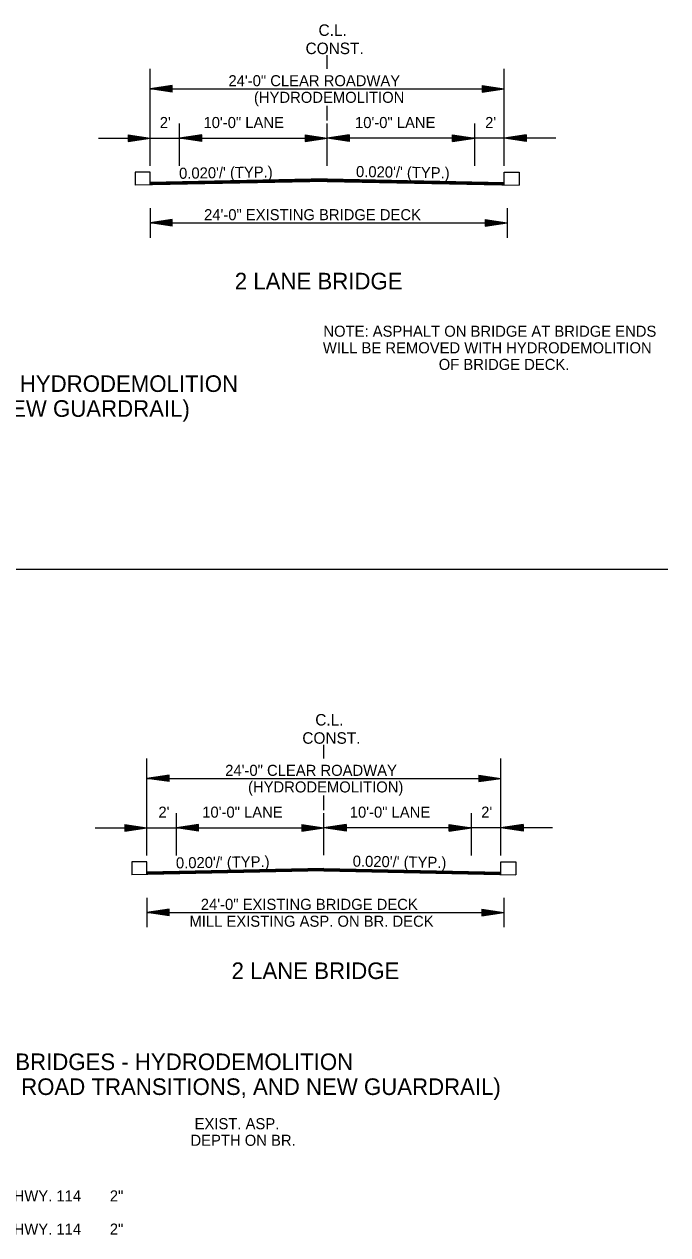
# Model space of a CAD drawing. Extents: x 544259 to 1930787, y -1961343 to 596640.
# Drawn here: x 544789 to 545226, y -1949576 to -1948755 of the extents above; entities that cross this region are included whole.
import ezdxf

# ---------------------------------------------------------------- set-up
doc = ezdxf.new("R2010")
doc.units = 0
doc.layers.add('R_Border', color=7, linetype='Continuous')
doc.layers.add('R_Draft', color=7, linetype='Continuous')

msp = doc.modelspace()

# ---------------------------------------------------------------- linework, layer by layer
at = {"layer": 'R_Border'}
for p, q in [((544864.6, -1948855.05), (544864.59, -1948863.86)), ((544874.77, -1948855.05), (544864.6, -1948855.05)), ((544874.77, -1948863.49), (544874.77, -1948855.05)), ((545114.77, -1948863.49), (545114.77, -1948855.05)), ((545114.77, -1948855.05), (545124.94, -1948855.05)), ((545124.94, -1948855.05), (545124.95, -1948863.86)), ((544266.84, -1949124.25), (545225.68, -1949124.25)), ((544862.4, -1949322.65), (544862.39, -1949331.46)), ((544872.57, -1949322.65), (544862.4, -1949322.65)), ((544872.57, -1949331.09), (544872.57, -1949322.65)), ((545112.57, -1949331.09), (545112.57, -1949322.65)), ((545112.57, -1949322.65), (545122.74, -1949322.65)), ((545122.74, -1949322.65), (545122.75, -1949331.46))]:
    msp.add_line(p, q, dxfattribs=at)
at = {"layer": 'R_Draft'}
for p, q in [((544994.77, -1948785.03), (544994.77, -1948775.73)), ((544874.77, -1948850.81), (544874.77, -1948785.08)), ((545114.77, -1948850.81), (545114.77, -1948785.08)), ((544889.77, -1948796.2), (544874.77, -1948798.45)), ((544874.77, -1948798.45), (545114.77, -1948798.45)), ((544889.77, -1948800.7), (544874.77, -1948798.45)), ((544889.77, -1948796.57), (544877.27, -1948798.45)), ((544889.77, -1948800.32), (544877.27, -1948798.45)), ((544889.77, -1948796.95), (544879.85, -1948798.45)), ((544889.77, -1948799.94), (544879.85, -1948798.45)), ((544889.77, -1948797.33), (544882.35, -1948798.45)), ((544889.77, -1948799.56), (544882.35, -1948798.45)), ((544889.77, -1948797.71), (544884.89, -1948798.45)), ((544889.77, -1948799.17), (544884.89, -1948798.45)), ((544889.77, -1948798.09), (544887.4, -1948798.45)), ((544889.77, -1948798.8), (544887.4, -1948798.45)), ((544889.77, -1948800.7), (544889.77, -1948796.2)), ((545099.77, -1948796.2), (545114.77, -1948798.45)), ((545099.77, -1948796.2), (545099.77, -1948800.7)), ((545099.77, -1948796.57), (545112.26, -1948798.45)), ((545099.77, -1948796.95), (545109.68, -1948798.45)), ((545099.77, -1948797.33), (545107.19, -1948798.45)), ((545099.77, -1948797.72), (545104.64, -1948798.45)), ((545099.77, -1948798.09), (545102.14, -1948798.45)), ((545099.77, -1948800.7), (545114.77, -1948798.45)), ((545099.77, -1948799.18), (545104.64, -1948798.45)), ((545099.77, -1948799.94), (545109.68, -1948798.45)), ((545099.77, -1948800.32), (545112.26, -1948798.45)), ((545099.77, -1948799.56), (545107.19, -1948798.45)), ((545099.77, -1948798.8), (545102.14, -1948798.45)), ((544994.77, -1948819.97), (544994.77, -1948810.1)), ((544894.77, -1948850.81), (544894.77, -1948822.09)), ((544994.77, -1948850.64), (544994.77, -1948822.09)), ((545094.77, -1948850.81), (545094.77, -1948822.09)), ((544839.77, -1948831.98), (544994.77, -1948831.98)), ((544859.77, -1948829.73), (544874.77, -1948831.98)), ((544859.77, -1948829.73), (544859.77, -1948834.23)), ((544859.77, -1948830.11), (544872.26, -1948831.98)), ((544859.77, -1948830.49), (544869.68, -1948831.98)), ((544859.77, -1948830.87), (544867.19, -1948831.98)), ((544859.77, -1948831.26), (544864.64, -1948831.98)), ((544859.77, -1948831.63), (544862.14, -1948831.98)), ((544859.77, -1948834.23), (544874.77, -1948831.98)), ((544859.77, -1948832.72), (544864.64, -1948831.98)), ((544859.77, -1948833.48), (544869.68, -1948831.98)), ((544859.77, -1948833.86), (544872.26, -1948831.98)), ((544859.77, -1948833.1), (544867.19, -1948831.98)), ((544859.77, -1948832.34), (544862.14, -1948831.98)), ((544909.77, -1948829.73), (544894.77, -1948831.98)), ((544909.77, -1948834.23), (544894.77, -1948831.98)), ((544909.77, -1948830.11), (544897.27, -1948831.98)), ((544909.77, -1948833.86), (544897.27, -1948831.98)), ((544909.77, -1948830.49), (544899.85, -1948831.98)), ((544909.77, -1948833.48), (544899.85, -1948831.98)), ((544909.77, -1948830.87), (544902.35, -1948831.98)), ((544909.77, -1948833.1), (544902.35, -1948831.98)), ((544909.77, -1948831.25), (544904.89, -1948831.98)), ((544909.77, -1948832.71), (544904.89, -1948831.98)), ((544909.77, -1948831.63), (544907.4, -1948831.98)), ((544909.77, -1948832.34), (544907.4, -1948831.98)), ((544909.77, -1948834.23), (544909.77, -1948829.73)), ((544979.77, -1948829.73), (544994.77, -1948831.98)), ((544979.77, -1948829.73), (544979.77, -1948834.23)), ((544979.77, -1948830.11), (544992.26, -1948831.98)), ((544979.77, -1948830.49), (544989.68, -1948831.98)), ((544979.77, -1948830.87), (544987.19, -1948831.98)), ((544979.77, -1948831.26), (544984.64, -1948831.98)), ((544979.77, -1948831.63), (544982.14, -1948831.98)), ((544979.77, -1948834.23), (544994.77, -1948831.98)), ((544979.77, -1948832.72), (544984.64, -1948831.98)), ((544979.77, -1948833.48), (544989.68, -1948831.98)), ((544979.77, -1948833.86), (544992.26, -1948831.98)), ((544979.77, -1948833.1), (544987.19, -1948831.98)), ((544979.77, -1948832.34), (544982.14, -1948831.98)), ((545009.77, -1948829.73), (544994.77, -1948831.98)), ((545149.77, -1948831.98), (544994.77, -1948831.98)), ((545009.77, -1948834.23), (544994.77, -1948831.98)), ((545009.77, -1948830.11), (544997.27, -1948831.98)), ((545009.77, -1948833.86), (544997.27, -1948831.98)), ((545009.77, -1948830.49), (544999.85, -1948831.98)), ((545009.77, -1948833.48), (544999.85, -1948831.98)), ((545009.77, -1948830.87), (545002.35, -1948831.98)), ((545009.77, -1948833.1), (545002.35, -1948831.98)), ((545009.77, -1948831.26), (545004.89, -1948831.98)), ((545009.77, -1948832.72), (545004.89, -1948831.98)), ((545009.77, -1948831.63), (545007.4, -1948831.98)), ((545009.77, -1948832.34), (545007.4, -1948831.98)), ((545009.77, -1948829.73), (545009.77, -1948834.23)), ((545079.77, -1948829.73), (545094.77, -1948831.98)), ((545079.77, -1948834.23), (545079.77, -1948829.73)), ((545079.77, -1948830.11), (545092.26, -1948831.98)), ((545079.77, -1948830.49), (545089.68, -1948831.98)), ((545079.77, -1948830.87), (545087.19, -1948831.98)), ((545079.77, -1948831.25), (545084.64, -1948831.98)), ((545079.77, -1948831.63), (545082.14, -1948831.98)), ((545079.77, -1948834.23), (545094.77, -1948831.98)), ((545079.77, -1948832.71), (545084.64, -1948831.98)), ((545079.77, -1948833.48), (545089.68, -1948831.98)), ((545079.77, -1948833.86), (545092.26, -1948831.98)), ((545079.77, -1948833.1), (545087.19, -1948831.98)), ((545079.77, -1948832.34), (545082.14, -1948831.98)), ((545129.77, -1948829.73), (545114.77, -1948831.98)), ((545129.77, -1948834.23), (545114.77, -1948831.98)), ((545129.77, -1948830.11), (545117.27, -1948831.98)), ((545129.77, -1948833.86), (545117.27, -1948831.98)), ((545129.77, -1948830.49), (545119.85, -1948831.98)), ((545129.77, -1948833.48), (545119.85, -1948831.98)), ((545129.77, -1948830.87), (545122.35, -1948831.98)), ((545129.77, -1948833.1), (545122.35, -1948831.98)), ((545129.77, -1948831.26), (545124.89, -1948831.98)), ((545129.77, -1948832.72), (545124.89, -1948831.98)), ((545129.77, -1948831.63), (545127.4, -1948831.98)), ((545129.77, -1948832.34), (545127.4, -1948831.98)), ((545129.77, -1948829.73), (545129.77, -1948834.23)), ((544994.8, -1948861.26), (544864.59, -1948863.86)), ((544994.77, -1948859.59), (544874.77, -1948861.99)), ((544994.77, -1948859.89), (544874.77, -1948862.29)), ((544994.78, -1948860.19), (544874.77, -1948862.59)), ((544994.79, -1948860.49), (544874.77, -1948862.89)), ((544994.79, -1948860.79), (544874.77, -1948863.19)), ((544994.8, -1948861.09), (544874.77, -1948863.49)), ((544994.74, -1948860.79), (545114.77, -1948863.19)), ((544994.74, -1948861.09), (545114.77, -1948863.49)), ((544994.74, -1948861.26), (545124.95, -1948863.86)), ((544994.75, -1948860.49), (545114.77, -1948862.89)), ((544994.76, -1948859.89), (545114.77, -1948862.29)), ((544994.76, -1948860.19), (545114.77, -1948862.59)), ((544994.77, -1948859.59), (545114.77, -1948861.99)), ((544874.77, -1948879.45), (544874.77, -1948899.45)), ((545116.77, -1948879.45), (545116.77, -1948899.45)), ((544889.77, -1948887.2), (544874.77, -1948889.45)), ((544874.77, -1948889.45), (545114.77, -1948889.45)), ((544889.77, -1948891.7), (544874.77, -1948889.45)), ((544889.77, -1948887.57), (544877.27, -1948889.45)), ((544889.77, -1948891.32), (544877.27, -1948889.45)), ((544889.77, -1948887.96), (544879.85, -1948889.45)), ((544889.77, -1948890.94), (544879.85, -1948889.45)), ((544889.77, -1948888.33), (544882.35, -1948889.45)), ((544889.77, -1948890.57), (544882.35, -1948889.45)), ((544889.77, -1948888.71), (544884.89, -1948889.45)), ((544889.77, -1948890.18), (544884.89, -1948889.45)), ((544889.77, -1948889.1), (544887.4, -1948889.45)), ((544889.77, -1948889.8), (544887.4, -1948889.45)), ((544889.77, -1948891.7), (544889.77, -1948887.2)), ((545101.77, -1948887.2), (545116.77, -1948889.45)), ((545101.77, -1948887.2), (545101.77, -1948891.7)), ((545101.77, -1948887.57), (545114.26, -1948889.45)), ((545101.77, -1948887.96), (545111.68, -1948889.45)), ((545101.77, -1948888.33), (545109.19, -1948889.45)), ((545101.77, -1948888.72), (545106.64, -1948889.45)), ((545101.77, -1948889.1), (545104.14, -1948889.45)), ((545101.77, -1948891.7), (545116.77, -1948889.45)), ((545101.77, -1948890.18), (545106.64, -1948889.45)), ((545101.77, -1948890.94), (545111.68, -1948889.45)), ((545101.77, -1948891.32), (545114.26, -1948889.45)), ((545101.77, -1948890.57), (545109.19, -1948889.45)), ((545101.77, -1948889.8), (545104.14, -1948889.45)), ((544992.57, -1949252.63), (544992.57, -1949243.32)), ((544872.57, -1949318.41), (544872.57, -1949252.67)), ((545112.57, -1949318.41), (545112.57, -1949252.67)), ((544887.57, -1949263.79), (544872.57, -1949266.04)), ((544872.57, -1949266.04), (545112.57, -1949266.04)), ((544887.57, -1949268.29), (544872.57, -1949266.04)), ((544887.57, -1949264.17), (544875.08, -1949266.04)), ((544887.57, -1949267.92), (544875.08, -1949266.04)), ((544887.57, -1949264.55), (544877.66, -1949266.04)), ((544887.57, -1949267.53), (544877.66, -1949266.04)), ((544887.57, -1949264.92), (544880.15, -1949266.04)), ((544887.57, -1949267.16), (544880.15, -1949266.04)), ((544887.57, -1949265.31), (544882.7, -1949266.04)), ((544887.57, -1949266.77), (544882.7, -1949266.04)), ((544887.57, -1949265.69), (544885.2, -1949266.04)), ((544887.57, -1949266.39), (544885.2, -1949266.04)), ((544887.57, -1949268.29), (544887.57, -1949263.79)), ((545097.57, -1949263.79), (545112.57, -1949266.04)), ((545097.57, -1949263.79), (545097.57, -1949268.29)), ((545097.57, -1949264.17), (545110.07, -1949266.04)), ((545097.57, -1949264.55), (545107.49, -1949266.04)), ((545097.57, -1949264.92), (545104.99, -1949266.04)), ((545097.57, -1949265.31), (545102.45, -1949266.04)), ((545097.57, -1949265.69), (545099.94, -1949266.04)), ((545097.57, -1949268.29), (545112.57, -1949266.04)), ((545097.57, -1949266.78), (545102.45, -1949266.04)), ((545097.57, -1949267.53), (545107.49, -1949266.04)), ((545097.57, -1949267.92), (545110.07, -1949266.04)), ((545097.57, -1949267.16), (545104.99, -1949266.04)), ((545097.57, -1949266.39), (545099.94, -1949266.04)), ((544992.57, -1949287.56), (544992.57, -1949277.69)), ((544892.57, -1949318.41), (544892.57, -1949289.69)), ((544992.57, -1949318.24), (544992.57, -1949289.69)), ((545092.57, -1949318.41), (545092.57, -1949289.69)), ((544837.57, -1949299.58), (544992.57, -1949299.58)), ((544857.57, -1949297.33), (544872.57, -1949299.58)), ((544857.57, -1949297.33), (544857.57, -1949301.83)), ((544857.57, -1949297.7), (544870.07, -1949299.58)), ((544857.57, -1949298.09), (544867.49, -1949299.58)), ((544857.57, -1949298.46), (544864.99, -1949299.58)), ((544857.57, -1949298.85), (544862.45, -1949299.58)), ((544857.57, -1949299.23), (544859.94, -1949299.58)), ((544857.57, -1949301.83), (544872.57, -1949299.58)), ((544857.57, -1949300.31), (544862.45, -1949299.58)), ((544857.57, -1949301.07), (544867.49, -1949299.58)), ((544857.57, -1949301.45), (544870.07, -1949299.58)), ((544857.57, -1949300.7), (544864.99, -1949299.58)), ((544857.57, -1949299.93), (544859.94, -1949299.58)), ((544907.57, -1949297.33), (544892.57, -1949299.58)), ((544907.57, -1949301.83), (544892.57, -1949299.58)), ((544907.57, -1949297.7), (544895.08, -1949299.58)), ((544907.57, -1949301.45), (544895.08, -1949299.58)), ((544907.57, -1949298.09), (544897.66, -1949299.58)), ((544907.57, -1949301.07), (544897.66, -1949299.58)), ((544907.57, -1949298.46), (544900.15, -1949299.58)), ((544907.57, -1949300.7), (544900.15, -1949299.58)), ((544907.57, -1949298.84), (544902.7, -1949299.58)), ((544907.57, -1949300.31), (544902.7, -1949299.58)), ((544907.57, -1949299.23), (544905.2, -1949299.58)), ((544907.57, -1949299.93), (544905.2, -1949299.58)), ((544907.57, -1949301.83), (544907.57, -1949297.33)), ((544977.57, -1949297.33), (544992.57, -1949299.58)), ((544977.57, -1949297.33), (544977.57, -1949301.83)), ((544977.57, -1949297.7), (544990.07, -1949299.58)), ((544977.57, -1949298.09), (544987.49, -1949299.58)), ((544977.57, -1949298.46), (544984.99, -1949299.58)), ((544977.57, -1949298.85), (544982.45, -1949299.58)), ((544977.57, -1949299.23), (544979.94, -1949299.58)), ((544977.57, -1949301.83), (544992.57, -1949299.58)), ((544977.57, -1949300.31), (544982.45, -1949299.58)), ((544977.57, -1949301.07), (544987.49, -1949299.58)), ((544977.57, -1949301.45), (544990.07, -1949299.58)), ((544977.57, -1949300.7), (544984.99, -1949299.58)), ((544977.57, -1949299.93), (544979.94, -1949299.58)), ((545007.57, -1949297.33), (544992.57, -1949299.58)), ((545147.57, -1949299.58), (544992.57, -1949299.58)), ((545007.57, -1949301.83), (544992.57, -1949299.58)), ((545007.57, -1949297.7), (544995.08, -1949299.58)), ((545007.57, -1949301.45), (544995.08, -1949299.58)), ((545007.57, -1949298.09), (544997.66, -1949299.58)), ((545007.57, -1949301.07), (544997.66, -1949299.58)), ((545007.57, -1949298.46), (545000.15, -1949299.58)), ((545007.57, -1949300.7), (545000.15, -1949299.58)), ((545007.57, -1949298.85), (545002.7, -1949299.58)), ((545007.57, -1949300.31), (545002.7, -1949299.58)), ((545007.57, -1949299.23), (545005.2, -1949299.58)), ((545007.57, -1949299.93), (545005.2, -1949299.58)), ((545007.57, -1949297.33), (545007.57, -1949301.83)), ((545077.57, -1949297.33), (545092.57, -1949299.58)), ((545077.57, -1949301.83), (545077.57, -1949297.33)), ((545077.57, -1949297.7), (545090.07, -1949299.58)), ((545077.57, -1949298.09), (545087.49, -1949299.58)), ((545077.57, -1949298.46), (545084.99, -1949299.58)), ((545077.57, -1949298.84), (545082.45, -1949299.58)), ((545077.57, -1949299.23), (545079.94, -1949299.58)), ((545077.57, -1949301.83), (545092.57, -1949299.58)), ((545077.57, -1949300.31), (545082.45, -1949299.58)), ((545077.57, -1949301.07), (545087.49, -1949299.58)), ((545077.57, -1949301.45), (545090.07, -1949299.58)), ((545077.57, -1949300.7), (545084.99, -1949299.58)), ((545077.57, -1949299.93), (545079.94, -1949299.58)), ((545127.57, -1949297.33), (545112.57, -1949299.58)), ((545127.57, -1949301.83), (545112.57, -1949299.58)), ((545127.57, -1949297.7), (545115.08, -1949299.58)), ((545127.57, -1949301.45), (545115.08, -1949299.58)), ((545127.57, -1949298.09), (545117.66, -1949299.58)), ((545127.57, -1949301.07), (545117.66, -1949299.58)), ((545127.57, -1949298.46), (545120.15, -1949299.58)), ((545127.57, -1949300.7), (545120.15, -1949299.58)), ((545127.57, -1949298.85), (545122.7, -1949299.58)), ((545127.57, -1949300.31), (545122.7, -1949299.58)), ((545127.57, -1949299.23), (545125.2, -1949299.58)), ((545127.57, -1949299.93), (545125.2, -1949299.58)), ((545127.57, -1949297.33), (545127.57, -1949301.83)), ((544992.6, -1949328.85), (544862.39, -1949331.46)), ((544992.57, -1949327.18), (544872.57, -1949329.58)), ((544992.58, -1949327.48), (544872.57, -1949329.88)), ((544992.58, -1949327.78), (544872.57, -1949330.18)), ((544992.59, -1949328.08), (544872.57, -1949330.48)), ((544992.59, -1949328.38), (544872.57, -1949330.78)), ((544992.6, -1949328.68), (544872.57, -1949331.09)), ((544992.54, -1949328.68), (545112.57, -1949331.09)), ((544992.54, -1949328.85), (545122.75, -1949331.46)), ((544992.55, -1949328.08), (545112.57, -1949330.48)), ((544992.55, -1949328.38), (545112.57, -1949330.78)), ((544992.56, -1949327.48), (545112.57, -1949329.88)), ((544992.56, -1949327.78), (545112.57, -1949330.18)), ((544992.57, -1949327.18), (545112.57, -1949329.58)), ((544872.57, -1949347.04), (544872.57, -1949367.04)), ((545114.57, -1949347.04), (545114.57, -1949367.04)), ((544887.57, -1949354.79), (544872.57, -1949357.04)), ((544872.57, -1949357.04), (545114.57, -1949357.04)), ((544887.57, -1949359.29), (544872.57, -1949357.04)), ((544887.57, -1949355.17), (544875.08, -1949357.04)), ((544887.57, -1949358.92), (544875.08, -1949357.04)), ((544887.57, -1949355.55), (544877.66, -1949357.04)), ((544887.57, -1949358.54), (544877.66, -1949357.04)), ((544887.57, -1949355.93), (544880.15, -1949357.04)), ((544887.57, -1949358.16), (544880.15, -1949357.04)), ((544887.57, -1949356.31), (544882.7, -1949357.04)), ((544887.57, -1949357.77), (544882.7, -1949357.04)), ((544887.57, -1949356.69), (544885.2, -1949357.04)), ((544887.57, -1949357.4), (544885.2, -1949357.04)), ((544887.57, -1949359.29), (544887.57, -1949354.79)), ((545099.57, -1949354.79), (545114.57, -1949357.04)), ((545099.57, -1949354.79), (545099.57, -1949359.29)), ((545099.57, -1949355.17), (545112.07, -1949357.04)), ((545099.57, -1949355.55), (545109.49, -1949357.04)), ((545099.57, -1949355.93), (545106.99, -1949357.04)), ((545099.57, -1949356.32), (545104.45, -1949357.04)), ((545099.57, -1949356.69), (545101.94, -1949357.04)), ((545099.57, -1949359.29), (545114.57, -1949357.04)), ((545099.57, -1949357.78), (545104.45, -1949357.04)), ((545099.57, -1949358.54), (545109.49, -1949357.04)), ((545099.57, -1949358.92), (545112.07, -1949357.04)), ((545099.57, -1949358.16), (545106.99, -1949357.04)), ((545099.57, -1949357.4), (545101.94, -1949357.04))]:
    msp.add_line(p, q, dxfattribs=at)

# ---------------------------------------------------------------- texts
for s, height, p in [('C.L.', 7.8, (544988.92, -1948762.63)), ('CONST.', 7.8, (544980.14, -1948775)), ('24\'-0" CLEAR ROADWAY ', 7.5, (544927.86, -1948796.78)), ('(HYDRODEMOLITION', 7.5, (544945.13, -1948808.03)), ("2'", 7.5, (544881.3, -1948825.12)), ('10\'-0" LANE', 7.5, (544910.93, -1948825.12)), ('10\'-0" LANE', 7.5, (545013.65, -1948825.12)), ("2'", 7.5, (545101.85, -1948825.12)), ('24\'-0" EXISTING BRIDGE DECK', 7.5, (544911.32, -1948887.62)), ('2 LANE BRIDGE', 11.25, (544932.17, -1948934.52)), ('NOTE: ASPHALT ON BRIDGE AT BRIDGE ENDS', 7.5, (544992.21, -1948966.63)), ('        WILL BE REMOVED WITH HYDRODEMOLITION', 7.5, (544969.57, -1948977.88)), ('OF BRIDGE DECK.                                          ', 7.5, (545070.4, -1948989.13)), ('24 FT. CLEAR ROADWAY BRIDGE - HYDRODEMOLITION', 11.25, (544531.47, -1949004.05)), ('(ROAD TRANSITIONS AND NEW GUARDRAIL)', 11.25, (544575.72, -1949020.92)), ('C.L.', 7.8, (544986.72, -1949230.23)), ('CONST.', 7.8, (544977.94, -1949242.6)), ('24\'-0" CLEAR ROADWAY ', 7.5, (544925.66, -1949264.37)), ('(HYDRODEMOLITION)', 7.5, (544941.13, -1949275.62)), ("2'", 7.5, (544880.38, -1949292.72)), ('10\'-0" LANE', 7.5, (544910.09, -1949292.72)), ('10\'-0" LANE', 7.5, (545010.09, -1949292.72)), ("2'", 7.5, (545099.18, -1949292.72)), ('24\'-0" EXISTING BRIDGE DECK', 7.5, (544909.13, -1949355.21)), ('MILL EXISTING ASP. ON BR. DECK', 7.5, (544901.42, -1949366.67)), ('2 LANE BRIDGE', 11.25, (544929.98, -1949402.12)), ('24 FT. CLEAR ROADWAY BRIDGES - HYDRODEMOLITION', 11.25, (544599.45, -1949463.85)), ('(BRIDGES WITH MILLING ON BR. DECKS, ROAD TRANSITIONS, AND NEW GUARDRAIL)', 11.25, (544487.26, -1949480.73)), (' EXIST. ASP. ', 7.5, (544902.13, -1949503.95)), ('DEPTH ON BR. ', 7.5, (544902.13, -1949515.2)), ('      2   - BR. NO. 02893 - HWY. 114       2"', 7.5, (544668.53, -1949552.92)), ('      3   - BR. NO. 02894 - HWY. 114       2"', 7.5, (544668.53, -1949575.42))]:
    msp.add_text(s, height=height, dxfattribs=at).set_placement(p)
for rotation, p in [(0.87191, (544894.44, -1948859.55)), (359.12809, (545014.27, -1948858.32)), (0.87191, (544892.3, -1949327.14)), (359.12809, (545012.06, -1949325.91))]:
    msp.add_text("0.020'/' (TYP.)", height=7.5, rotation=rotation, dxfattribs=at).set_placement(p)

doc.saveas('drawing.dxf')
